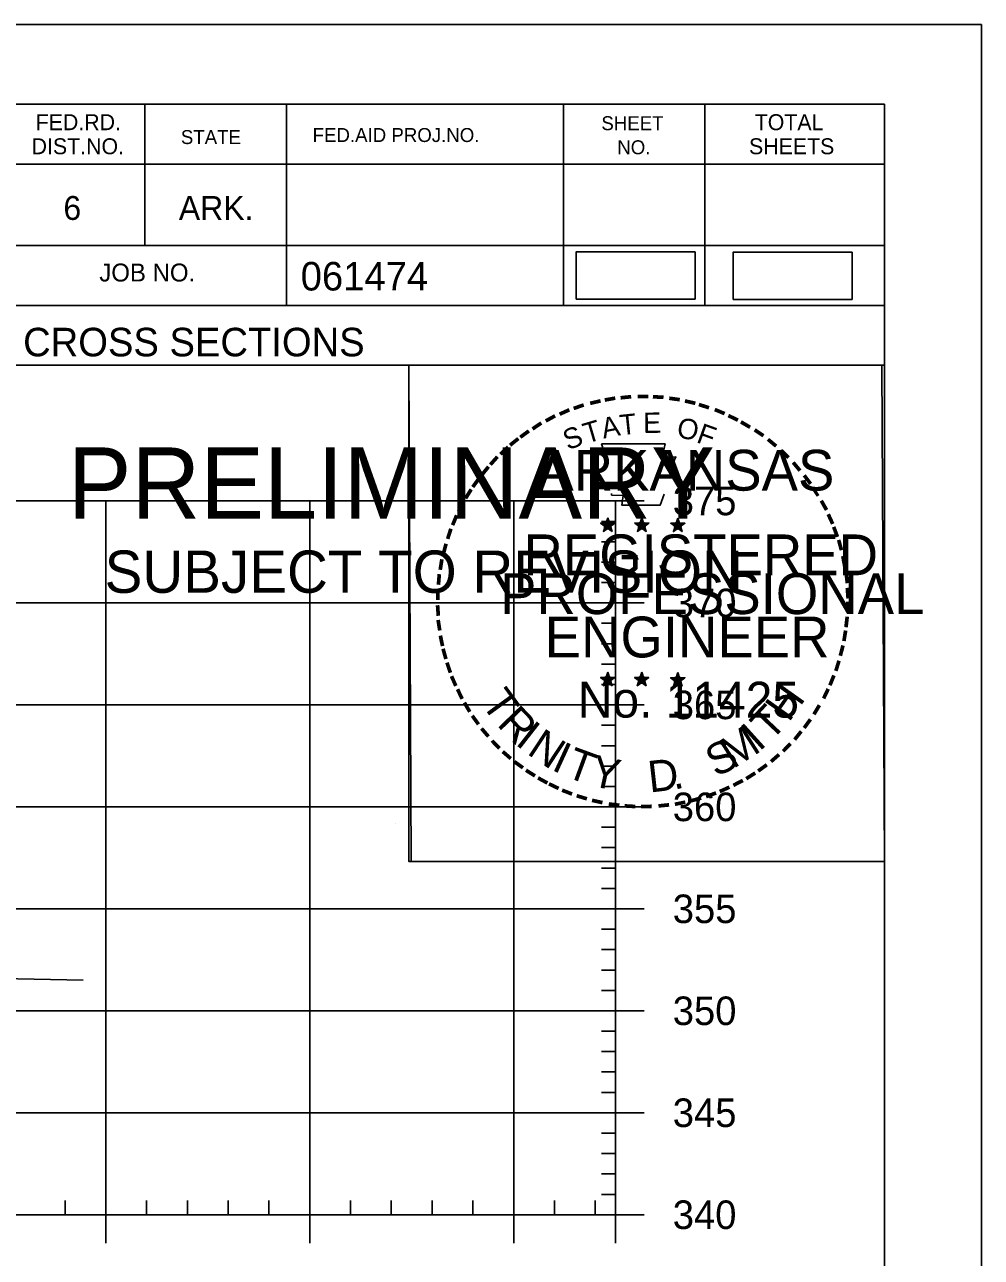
# Model space of a CAD drawing. Extents: x 1359801 to 1362404, y 372415 to 374228.
# Drawn here: x 1360087.4 to 1360134.3, y 372674.2 to 372734.6 of the extents above; entities that cross this region are included whole.
import ezdxf

# ---------------------------------------------------------------- set-up
doc = ezdxf.new("R2010")
doc.units = 0
for name, color, linetype in [('S_DRG_PT_SYM', 7, 'Continuous'), ('S_MAILBOX', 7, 'Continuous'), ('S_PRIMARY_CTL', 7, 'Continuous'), ('S_PRIMARY_CTL_ANNOT', 7, 'Continuous'), ('S_SHOULDER', 7, 'Continuous'), ('S_TELEPHONE_UTILITIES', 7, 'Continuous'), ('S_UNDERGROUND_CABLE', 7, 'Continuous'), ('S_UTL_PT_SYM', 7, 'Continuous'), ('S_WATER_UTILITIES', 7, 'Continuous')]:
    doc.layers.add(name, color=color, linetype=linetype)

msp = doc.modelspace()

# ---------------------------------------------------------------- linework, layer by layer
at = {"layer": 'S_DRG_PT_SYM'}
msp.add_lwpolyline([(1360041.985, 372702.382), (1360044.112, 372702.288), (1360045.515, 372701.937), (1360047.173, 372701.553), (1360050.102, 372700.495), (1360053.466, 372699.458), (1360054.553, 372699.222), (1360056.36, 372698.808), (1360058.299, 372693.016), (1360058.699, 372692.992), (1360063.297, 372688.326), (1360077.511, 372688.018), (1360082.996, 372687.899), (1360090.239, 372687.742)], dxfattribs=at)
at = {"layer": 'S_MAILBOX'}
for p, q in [((1359826.35, 372711.245), (1360116.35, 372711.245)), ((1360091.35, 372676.245), (1360091.35, 372711.245)), ((1360101.35, 372676.245), (1360101.35, 372711.245)), ((1360111.35, 372676.245), (1360111.35, 372711.245)), ((1360116.35, 372676.245), (1360116.35, 372711.245)), ((1359826.35, 372706.245), (1360116.35, 372706.245)), ((1359826.35, 372701.245), (1360116.35, 372701.245)), ((1359826.35, 372696.245), (1360116.35, 372696.245)), ((1359826.35, 372691.245), (1360116.35, 372691.245)), ((1359826.35, 372686.245), (1360116.35, 372686.245)), ((1359826.35, 372681.245), (1360116.35, 372681.245)), ((1359826.35, 372676.245), (1360116.35, 372676.245))]:
    msp.add_line(p, q, dxfattribs=at)
at = {"layer": 'S_SHOULDER'}
for p, q in [((1359800.949, 372734.6), (1360134.283, 372734.6)), ((1360105.565, 372695.45), (1360105.565, 372695.45))]:
    msp.add_line(p, q, dxfattribs=at)
for points in [[(1359800.943, 372734.6), (1360134.283, 372734.6), (1360134.283, 372521.263), (1359800.943, 372521.263)], [(1360047.27, 372730.706), (1360047.27, 372720.826), (1360083.002, 372720.826), (1360083.002, 372717.906), (1360106.202, 372717.906), (1360106.202, 372693.573), (1360129.53, 372693.573), (1360129.53, 372525.246), (1359813.35, 372525.246), (1359813.35, 372730.706)], [(1360106.202, 372717.906), (1360129.41, 372717.906), (1360129.53, 372693.573), (1360106.322, 372693.573)]]:
    msp.add_lwpolyline(points, close=True, dxfattribs=at)
at = {"layer": 'S_TELEPHONE_UTILITIES'}
for p, q in [((1360115.615, 372710.161), (1360115.964, 372710.05)), ((1360115.615, 372710.161), (1360115.868, 372710.116)), ((1360115.615, 372710.161), (1360115.852, 372710.039)), ((1360115.748, 372709.753), (1360115.964, 372710.05)), ((1360115.964, 372710.415), (1360115.923, 372710.163)), ((1360115.964, 372710.05), (1360115.964, 372710.415)), ((1360115.964, 372710.415), (1360116.013, 372710.165)), ((1360116.311, 372710.161), (1360115.964, 372710.05)), ((1360116.177, 372709.753), (1360115.964, 372710.05)), ((1360116.311, 372710.161), (1360116.025, 372710.112)), ((1360116.177, 372709.753), (1360116.04, 372710.044)), ((1360116.311, 372710.161), (1360116.107, 372710.059)), ((1360117.285, 372710.161), (1360117.634, 372710.05)), ((1360117.285, 372710.161), (1360117.538, 372710.116)), ((1360117.285, 372710.161), (1360117.522, 372710.039)), ((1360117.418, 372709.753), (1360117.634, 372710.05)), ((1360117.634, 372710.415), (1360117.593, 372710.163)), ((1360117.634, 372710.05), (1360117.634, 372710.415)), ((1360117.634, 372710.415), (1360117.683, 372710.165)), ((1360117.981, 372710.161), (1360117.634, 372710.05)), ((1360117.847, 372709.753), (1360117.634, 372710.05)), ((1360117.981, 372710.161), (1360117.695, 372710.112)), ((1360117.847, 372709.753), (1360117.71, 372710.044)), ((1360117.981, 372710.161), (1360117.777, 372710.059)), ((1360119.049, 372710.149), (1360119.398, 372710.038)), ((1360119.049, 372710.149), (1360119.302, 372710.104)), ((1360119.049, 372710.149), (1360119.286, 372710.027)), ((1360119.182, 372709.741), (1360119.398, 372710.038)), ((1360119.398, 372710.403), (1360119.357, 372710.151)), ((1360119.398, 372710.038), (1360119.398, 372710.403)), ((1360119.398, 372710.403), (1360119.447, 372710.153)), ((1360119.745, 372710.149), (1360119.398, 372710.038)), ((1360119.611, 372709.741), (1360119.398, 372710.038)), ((1360119.745, 372710.149), (1360119.459, 372710.1)), ((1360119.611, 372709.741), (1360119.474, 372710.032)), ((1360119.745, 372710.149), (1360119.541, 372710.047)), ((1360115.748, 372709.753), (1360115.874, 372709.997)), ((1360115.748, 372709.753), (1360115.962, 372709.97)), ((1360116.177, 372709.753), (1360115.962, 372709.967)), ((1360117.418, 372709.753), (1360117.544, 372709.997)), ((1360117.418, 372709.753), (1360117.632, 372709.97)), ((1360117.847, 372709.753), (1360117.632, 372709.967)), ((1360119.182, 372709.741), (1360119.308, 372709.985)), ((1360119.182, 372709.741), (1360119.396, 372709.958)), ((1360119.611, 372709.741), (1360119.396, 372709.955)), ((1360115.96, 372702.842), (1360115.919, 372702.59)), ((1360115.96, 372702.477), (1360115.96, 372702.842)), ((1360115.96, 372702.842), (1360116.009, 372702.592)), ((1360117.629, 372702.842), (1360117.588, 372702.59)), ((1360117.629, 372702.477), (1360117.629, 372702.842)), ((1360117.629, 372702.842), (1360117.678, 372702.592)), ((1360119.396, 372702.832), (1360119.355, 372702.58)), ((1360119.396, 372702.467), (1360119.396, 372702.832)), ((1360119.396, 372702.832), (1360119.445, 372702.582)), ((1360115.611, 372702.588), (1360115.96, 372702.477)), ((1360115.611, 372702.588), (1360115.864, 372702.543)), ((1360115.611, 372702.588), (1360115.848, 372702.466)), ((1360115.744, 372702.18), (1360115.96, 372702.477)), ((1360115.744, 372702.18), (1360115.87, 372702.424)), ((1360115.744, 372702.18), (1360115.958, 372702.397)), ((1360116.173, 372702.18), (1360115.958, 372702.394)), ((1360116.307, 372702.588), (1360115.96, 372702.477)), ((1360116.173, 372702.18), (1360115.96, 372702.477)), ((1360116.307, 372702.588), (1360116.021, 372702.539)), ((1360116.173, 372702.18), (1360116.036, 372702.471)), ((1360116.307, 372702.588), (1360116.103, 372702.486)), ((1360117.28, 372702.588), (1360117.629, 372702.477)), ((1360117.28, 372702.588), (1360117.533, 372702.543)), ((1360117.28, 372702.588), (1360117.517, 372702.466)), ((1360117.413, 372702.18), (1360117.629, 372702.477)), ((1360117.413, 372702.18), (1360117.539, 372702.424)), ((1360117.413, 372702.18), (1360117.627, 372702.397)), ((1360117.842, 372702.18), (1360117.627, 372702.394)), ((1360117.976, 372702.588), (1360117.629, 372702.477)), ((1360117.842, 372702.18), (1360117.629, 372702.477)), ((1360117.976, 372702.588), (1360117.69, 372702.539)), ((1360117.842, 372702.18), (1360117.705, 372702.471)), ((1360117.976, 372702.588), (1360117.772, 372702.486)), ((1360119.047, 372702.578), (1360119.396, 372702.467)), ((1360119.047, 372702.578), (1360119.3, 372702.533)), ((1360119.047, 372702.578), (1360119.284, 372702.456)), ((1360119.18, 372702.17), (1360119.396, 372702.467)), ((1360119.18, 372702.17), (1360119.306, 372702.414)), ((1360119.18, 372702.17), (1360119.394, 372702.387)), ((1360119.609, 372702.17), (1360119.394, 372702.384)), ((1360119.743, 372702.578), (1360119.396, 372702.467)), ((1360119.609, 372702.17), (1360119.396, 372702.467)), ((1360119.743, 372702.578), (1360119.457, 372702.529)), ((1360119.609, 372702.17), (1360119.472, 372702.461)), ((1360119.743, 372702.578), (1360119.539, 372702.476))]:
    msp.add_line(p, q, dxfattribs=at)
for points in [[(1360115.656, 372714.039), (1360115.925, 372713.212)], [(1360119.167, 372713.117), (1360119.309, 372713.401), (1360118.624, 372713.377), (1360118.772, 372714.039), (1360115.656, 372714.039)], [(1360116.148, 372711.616), (1360116.148, 372711.529), (1360116.711, 372711.51), (1360116.657, 372711.037), (1360118.527, 372711.037), (1360118.728, 372711.573)], [(1360115.964, 372710.415), (1360116.177, 372709.753), (1360115.615, 372710.161), (1360116.311, 372710.161), (1360115.748, 372709.753), (1360115.964, 372710.415)], [(1360117.634, 372710.415), (1360117.847, 372709.753), (1360117.285, 372710.161), (1360117.981, 372710.161), (1360117.418, 372709.753), (1360117.634, 372710.415)], [(1360119.398, 372710.403), (1360119.611, 372709.741), (1360119.049, 372710.149), (1360119.745, 372710.149), (1360119.182, 372709.741), (1360119.398, 372710.403)], [(1360115.96, 372702.842), (1360116.173, 372702.18), (1360115.611, 372702.588), (1360116.307, 372702.588), (1360115.744, 372702.18), (1360115.96, 372702.842)], [(1360117.629, 372702.842), (1360117.842, 372702.18), (1360117.28, 372702.588), (1360117.976, 372702.588), (1360117.413, 372702.18), (1360117.629, 372702.842)], [(1360119.396, 372702.832), (1360119.609, 372702.17), (1360119.047, 372702.578), (1360119.743, 372702.578), (1360119.18, 372702.17), (1360119.396, 372702.832)]]:
    msp.add_lwpolyline(points, dxfattribs=at)
for centre, radius in [((1360115.963, 372710.049), 0.172), ((1360115.963, 372710.049), 0.145), ((1360115.963, 372710.049), 0.116), ((1360115.963, 372710.049), 0.0991), ((1360115.963, 372710.049), 0.0747), ((1360115.963, 372710.049), 0.0495), ((1360115.963, 372710.049), 0.0296), ((1360117.633, 372710.049), 0.172), ((1360117.633, 372710.049), 0.145), ((1360117.633, 372710.049), 0.116), ((1360117.633, 372710.049), 0.0991), ((1360117.633, 372710.049), 0.0747), ((1360117.633, 372710.049), 0.0495), ((1360117.633, 372710.049), 0.0296), ((1360119.397, 372710.037), 0.172), ((1360119.397, 372710.037), 0.145), ((1360119.397, 372710.037), 0.116), ((1360119.397, 372710.037), 0.0991), ((1360119.397, 372710.037), 0.0747), ((1360119.397, 372710.037), 0.0495), ((1360119.397, 372710.037), 0.0296), ((1360115.959, 372702.476), 0.172), ((1360115.959, 372702.476), 0.145), ((1360115.959, 372702.476), 0.116), ((1360115.959, 372702.476), 0.0991), ((1360115.959, 372702.476), 0.0747), ((1360115.959, 372702.476), 0.0495), ((1360115.959, 372702.476), 0.0296), ((1360117.628, 372702.476), 0.172), ((1360117.628, 372702.476), 0.145), ((1360117.628, 372702.476), 0.116), ((1360117.628, 372702.476), 0.0991), ((1360117.628, 372702.476), 0.0747), ((1360117.628, 372702.476), 0.0495), ((1360117.628, 372702.476), 0.0296), ((1360119.395, 372702.466), 0.172), ((1360119.395, 372702.466), 0.145), ((1360119.395, 372702.466), 0.116), ((1360119.395, 372702.466), 0.0991), ((1360119.395, 372702.466), 0.0747), ((1360119.395, 372702.466), 0.0495), ((1360119.395, 372702.466), 0.0296)]:
    msp.add_circle(centre, radius, dxfattribs=at)
at = {"layer": 'S_UNDERGROUND_CABLE'}
for points in [[(1360114.413, 372721.144), (1360120.246, 372721.144), (1360120.246, 372723.455), (1360114.413, 372723.455)], [(1360122.109, 372721.13), (1360127.942, 372721.13), (1360127.942, 372723.44), (1360122.109, 372723.44)]]:
    msp.add_lwpolyline(points, close=True, dxfattribs=at)
at = {"layer": 'S_UTL_PT_SYM'}
for p, q in [((1359813.35, 372730.706), (1360129.53, 372730.706)), ((1360093.27, 372730.706), (1360093.27, 372723.766)), ((1360100.21, 372730.706), (1360100.21, 372720.826)), ((1360113.79, 372730.706), (1360113.79, 372720.826)), ((1360120.73, 372730.706), (1360120.73, 372720.826)), ((1360129.53, 372525.246), (1360129.53, 372730.706)), ((1360129.53, 372727.766), (1360086.43, 372727.766)), ((1360129.53, 372727.786), (1360129.53, 372727.786)), ((1360129.53, 372723.766), (1360086.43, 372723.766)), ((1360089.39, 372723.766), (1360129.53, 372723.766)), ((1360129.53, 372720.826), (1360047.27, 372720.826)), ((1360086.43, 372717.906), (1360129.53, 372717.906))]:
    msp.add_line(p, q, dxfattribs=at)
at = {"layer": 'S_WATER_UTILITIES'}
for p, q in [((1360116.35, 372676.245), (1360116.35, 372711.245)), ((1360117.75, 372711.245), (1360116.35, 372711.245)), ((1360116.35, 372710.245), (1360115.65, 372710.245)), ((1360116.35, 372709.245), (1360115.65, 372709.245)), ((1360116.35, 372708.245), (1360115.65, 372708.245)), ((1360116.35, 372707.245), (1360115.65, 372707.245)), ((1360117.75, 372706.245), (1360116.35, 372706.245)), ((1360116.35, 372705.245), (1360115.65, 372705.245)), ((1360116.35, 372704.245), (1360115.65, 372704.245)), ((1360116.35, 372703.245), (1360115.65, 372703.245)), ((1360116.35, 372702.245), (1360115.65, 372702.245)), ((1360117.75, 372701.245), (1360116.35, 372701.245)), ((1360116.35, 372700.245), (1360115.65, 372700.245)), ((1360116.35, 372699.245), (1360115.65, 372699.245)), ((1360116.35, 372698.245), (1360115.65, 372698.245)), ((1360116.35, 372697.245), (1360115.65, 372697.245)), ((1360117.75, 372696.245), (1360116.35, 372696.245)), ((1360116.35, 372695.245), (1360115.65, 372695.245)), ((1360116.35, 372694.245), (1360115.65, 372694.245)), ((1360116.35, 372693.245), (1360115.65, 372693.245)), ((1360116.35, 372692.245), (1360115.65, 372692.245)), ((1360117.75, 372691.245), (1360116.35, 372691.245)), ((1360116.35, 372690.245), (1360115.65, 372690.245)), ((1360116.35, 372689.245), (1360115.65, 372689.245)), ((1360116.35, 372688.245), (1360115.65, 372688.245)), ((1360116.35, 372687.245), (1360115.65, 372687.245)), ((1360117.75, 372686.245), (1360116.35, 372686.245)), ((1360116.35, 372685.245), (1360115.65, 372685.245)), ((1360116.35, 372684.245), (1360115.65, 372684.245)), ((1360116.35, 372683.245), (1360115.65, 372683.245)), ((1360116.35, 372682.245), (1360115.65, 372682.245)), ((1360117.75, 372681.245), (1360116.35, 372681.245)), ((1360116.35, 372680.245), (1360115.65, 372680.245)), ((1360116.35, 372679.245), (1360115.65, 372679.245)), ((1360116.35, 372678.245), (1360115.65, 372678.245)), ((1360089.35, 372676.245), (1360089.35, 372676.945)), ((1360093.35, 372676.245), (1360093.35, 372676.945)), ((1360095.35, 372676.245), (1360095.35, 372676.945)), ((1360097.35, 372676.245), (1360097.35, 372676.945)), ((1360099.35, 372676.245), (1360099.35, 372676.945)), ((1360103.35, 372676.245), (1360103.35, 372676.945)), ((1360105.35, 372676.245), (1360105.35, 372676.945)), ((1360107.35, 372676.245), (1360107.35, 372676.945)), ((1360109.35, 372676.245), (1360109.35, 372676.945)), ((1360113.35, 372676.245), (1360113.35, 372676.945)), ((1360115.35, 372676.245), (1360115.35, 372676.945)), ((1360116.35, 372677.245), (1360115.65, 372677.245)), ((1359826.35, 372676.245), (1360116.35, 372676.245)), ((1360091.35, 372674.845), (1360091.35, 372676.245)), ((1360101.35, 372674.845), (1360101.35, 372676.245)), ((1360111.35, 372674.845), (1360111.35, 372676.245)), ((1360116.35, 372674.845), (1360116.35, 372676.245)), ((1360117.75, 372676.245), (1360116.35, 372676.245))]:
    msp.add_line(p, q, dxfattribs=at)

# ---------------------------------------------------------------- texts
at = {"layer": 'S_PRIMARY_CTL'}
for s, p in [('375', (1360119.15, 372710.545)), ('370', (1360119.15, 372705.545)), ('365', (1360119.15, 372700.545)), ('360', (1360119.15, 372695.545)), ('355', (1360119.15, 372690.545)), ('350', (1360119.15, 372685.545)), ('345', (1360119.15, 372680.545)), ('340', (1360119.15, 372675.545))]:
    msp.add_text(s, height=1.4, dxfattribs=at).set_placement(p)
at = {"layer": 'S_PRIMARY_CTL_ANNOT'}
for s, height, p in [('PRELIMINARY', 3.5, (1360089.481, 372710.369)), ('DWB', 0.01, (1360090.228, 372712.218)), ('SUBJECT TO REVISION', 2.07511, (1360091.29, 372706.74))]:
    msp.add_text(s, height=height, rotation=360, dxfattribs=at).set_placement(p)
at = {"layer": 'S_TELEPHONE_UTILITIES'}
for s, height, rotation, p in [('-', 1.6, 13.63015, (1360115.154, 372715.407)), ('-', 1.6, 10.21935, (1360115.832, 372715.569)), ('-', 1.6, 5.89682, (1360116.561, 372715.679)), ('-', 1.6, 0.18623, (1360117.333, 372715.751)), ('-', 1.6, 357.74304, (1360118.056, 372715.738)), ('-', 1.6, 352.16172, (1360118.8, 372715.682)), ('-', 1.6, 347.20489, (1360119.519, 372715.568)), ('-', 1.6, 342.3362, (1360120.154, 372715.413)), ('-', 1.6, 28.79182, (1360113.137, 372714.58)), ('-', 1.6, 24.30721, (1360113.77, 372714.897)), ('-', 1.6, 19.17608, (1360114.404, 372715.166)), ('T', 1, 6.02276, (1360116.6, 372714.465)), ('E', 1, 0.83234, (1360117.705, 372714.575)), ('-', 1.6, 337.85509, (1360120.889, 372715.19)), ('-', 1.6, 334.12109, (1360121.52, 372714.919)), ('-', 1.6, 34.06357, (1360112.54, 372714.21)), ('S', 1, 21.59401, (1360114.011, 372713.717)), ('T', 1, 16.4036, (1360114.925, 372714.048)), ('A', 1, 11.21318, (1360115.751, 372714.299)), ('O', 1, 350.4515, (1360119.309, 372714.365)), ('F', 1, 340.07066, (1360120.263, 372714.137)), ('-', 1.6, 329.64089, (1360122.099, 372714.636)), ('-', 1.6, 38.95066, (1360111.486, 372713.437)), ('-', 1.6, 36.23174, (1360111.962, 372713.815)), ('-', 1.6, 325.86266, (1360122.742, 372714.275)), ('-', 1.6, 320.52971, (1360123.352, 372713.849)), ('-', 1.6, 42.96224, (1360111.053, 372713.02)), ('ARKANSAS', 2, 360, (1360112.509, 372711.751)), ('-', 1.6, 315.57859, (1360123.951, 372713.361)), ('-', 1.6, 48.42305, (1360110.605, 372712.542)), ('-', 1.6, 309.87973, (1360124.52, 372712.811)), ('-', 1.6, 50.61417, (1360110.202, 372712.056)), ('-', 1.6, 306.65218, (1360125.045, 372712.209)), ('-', 1.6, 58.07063, (1360109.464, 372710.962)), ('-', 1.6, 54.23247, (1360109.789, 372711.489)), ('-', 1.4, 303.67529, (1360125.531, 372711.641)), ('-', 1.6, 62.87135, (1360109.151, 372710.348)), ('-', 1.6, 299.66835, (1360125.85, 372711.034)), ('-', 1.6, 294.66279, (1360126.174, 372710.422)), ('-', 1.6, 67.77427, (1360108.892, 372709.737)), ('DWB', 0.01, 360, (1360115.951, 372710.045)), ('DWB', 0.01, 360, (1360117.621, 372710.045)), ('DWB', 0.01, 360, (1360119.385, 372710.034)), ('-', 1.6, 72.39447, (1360108.673, 372709.107)), ('REGISTERED', 2, 360, (1360111.831, 372707.602)), ('-', 1.6, 290.57283, (1360126.431, 372709.845)), ('-', 1.6, 75.46096, (1360108.476, 372708.393)), ('-', 1.6, 285.12326, (1360126.665, 372709.265)), ('-', 1.6, 81.20126, (1360108.344, 372707.68)), ('-', 1.6, 280.54934, (1360126.865, 372708.523)), ('-', 1.6, 85.18634, (1360108.268, 372706.989)), ('PROFESSIONAL', 2, 360, (1360110.683, 372705.698)), ('-', 1.6, 276.59616, (1360127.027, 372707.755)), ('-', 1.6, 274.33011, (1360127.087, 372707.033)), ('-', 1.6, 89.06224, (1360108.243, 372706.288)), ('-', 1.6, 94.19588, (1360108.278, 372705.563)), ('-', 1.6, 269.94067, (1360127.121, 372706.401)), ('-', 1.6, 98.94793, (1360108.35, 372704.896)), ('ENGINEER', 2, 360, (1360112.87, 372703.573)), ('-', 1.6, 263.5172, (1360127.102, 372705.735)), ('-', 1.6, 101.71495, (1360108.485, 372704.163)), ('-', 1.6, 260.99529, (1360127.031, 372705.081)), ('-', 1.6, 105.45785, (1360108.647, 372703.568)), ('-', 1.6, 255.7626, (1360126.921, 372704.403)), ('-', 1.6, 252.86809, (1360126.74, 372703.683)), ('-', 1.6, 109.08742, (1360108.862, 372702.937)), ('-', 1.6, 114.06432, (1360109.116, 372702.341)), ('T', 1.54, 306.04056, (1360109.72, 372701.315)), ('No. 11425', 1.757, 360, (1360114.498, 372700.622)), ('DWB', 0.01, 360, (1360115.947, 372702.472)), ('DWB', 0.01, 360, (1360117.616, 372702.472)), ('DWB', 0.01, 360, (1360119.383, 372702.462)), ('H', 1.54, 54.60883, (1360124.84, 372700.35)), ('-', 1.6, 247.88866, (1360126.517, 372703.01)), ('-', 1.6, 115.72885, (1360109.421, 372701.723)), ('-', 1.6, 244.61971, (1360126.255, 372702.381)), ('-', 1.6, 120.44712, (1360109.778, 372701.137)), ('R', 1.54, 314.00497, (1360110.482, 372700.267)), ('T', 1.54, 46.64442, (1360123.95, 372699.408)), ('-', 1.6, 239.07125, (1360125.861, 372701.629)), ('-', 1.6, 125.89344, (1360110.181, 372700.576)), ('I', 1.54, 321.96938, (1360111.383, 372699.335)), ('-', 1.6, 233.84524, (1360125.459, 372700.976)), ('-', 1.6, 130.71812, (1360110.643, 372700.024)), ('N', 1.54, 326.50021, (1360111.95, 372698.864)), ('M', 1.54, 32.65632, (1360122.105, 372698.083)), ('I', 1.54, 42.11359, (1360123.389, 372698.93)), ('-', 1.6, 231.25377, (1360125.029, 372700.41)), ('-', 1.6, 134.22381, (1360111.16, 372699.479)), ('I', 1.54, 335.36034, (1360113.158, 372698.078)), ('T', 1.54, 339.89117, (1360113.819, 372697.75)), ('S', 1.54, 26.9312, (1360121.266, 372697.677)), ('-', 1.6, 225.76533, (1360124.55, 372699.846)), ('-', 1.6, 138.93382, (1360111.685, 372699.015)), ('-', 1.6, 144.64634, (1360112.241, 372698.609)), ('Y', 1.54, 347.85558, (1360115.036, 372697.305)), ('D', 1.54, 6.39691, (1360118.021, 372696.946)), ('-', 1.6, 221.08509, (1360124.028, 372699.337)), ('-', 1.6, 148.08978, (1360112.802, 372698.238)), ('-', 1.6, 212.24909, (1360122.945, 372698.478)), ('-', 1.6, 215.73633, (1360123.479, 372698.865)), ('-', 1.6, 151.57039, (1360113.381, 372697.913)), ('-', 1.6, 154.60019, (1360113.903, 372697.666)), ('.', 1.54, 13.76417, (1360119.213, 372697.074)), ('-', 1.6, 207.35684, (1360122.387, 372698.132)), ('-', 1.6, 158.56121, (1360114.527, 372697.412)), ('-', 1.6, 162.79826, (1360115.214, 372697.199)), ('-', 1.6, 195.47429, (1360120.467, 372697.298)), ('-', 1.6, 200.71842, (1360121.144, 372697.54)), ('-', 1.6, 204.25161, (1360121.763, 372697.813)), ('-', 1.6, 167.55551, (1360115.929, 372697.035)), ('-', 1.6, 173.11546, (1360116.701, 372696.925)), ('-', 1.6, 176.51827, (1360117.449, 372696.872)), ('-', 1.6, 181.59176, (1360118.193, 372696.891)), ('-', 1.6, 185.81666, (1360119.002, 372696.967)), ('-', 1.6, 191.28576, (1360119.738, 372697.099))]:
    msp.add_text(s, height=height, rotation=rotation, dxfattribs=at).set_placement(p)
at = {"layer": 'S_UTL_PT_SYM'}
for s, height, p in [('FED.RD.', 0.7819, (1360087.91, 372729.426)), ('SHEET', 0.684, (1360115.65, 372729.426)), ('TOTAL', 0.7819, (1360123.17, 372729.426)), ('STATE', 0.684, (1360095.03, 372728.746)), ('FED.AID PROJ.NO.', 0.684, (1360101.49, 372728.846)), ('DIST.NO.', 0.7819, (1360087.71, 372728.246)), ('NO.', 0.684, (1360116.43, 372728.246)), ('SHEETS', 0.7819, (1360122.89, 372728.246)), ('6', 1.172, (1360089.27, 372725.026)), ('ARK.', 1.1723, (1360094.93, 372725.026)), ('JOB NO.', 0.8792, (1360091.03, 372722.006)), ('061474', 1.4, (1360100.906, 372721.565)), ('CROSS SECTIONS', 1.4, (1360087.294, 372718.336))]:
    msp.add_text(s, height=height, rotation=360, dxfattribs=at).set_placement(p)

doc.saveas('drawing.dxf')
